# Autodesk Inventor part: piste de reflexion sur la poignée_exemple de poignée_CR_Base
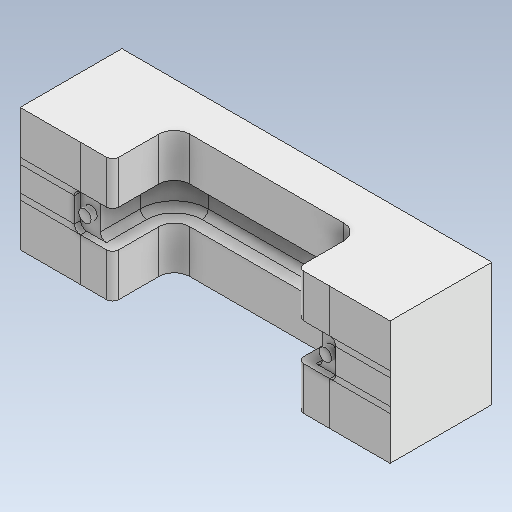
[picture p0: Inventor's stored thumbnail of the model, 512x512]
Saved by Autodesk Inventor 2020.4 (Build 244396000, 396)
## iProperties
Created: 2021-10
Part Number: piste de reflexion sur la poignée_exemple de poignée_CR_Base
Material: Générique
Document SubType Name: Modeling
Designer: mel
Density: 1 g/cm^3
Appearance: Par défaut
Author: mel
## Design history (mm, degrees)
node "piste de reflexion sur la poignée_exemple de poignée_MP"
feature "Solide3::piste de reflexion sur la poignée_exemple de poigné"
tag "FonctionRepérage1"
node "Solide1"
feature "piste de reflexion sur la poignée_exemple de poignée_MP_Corp"
